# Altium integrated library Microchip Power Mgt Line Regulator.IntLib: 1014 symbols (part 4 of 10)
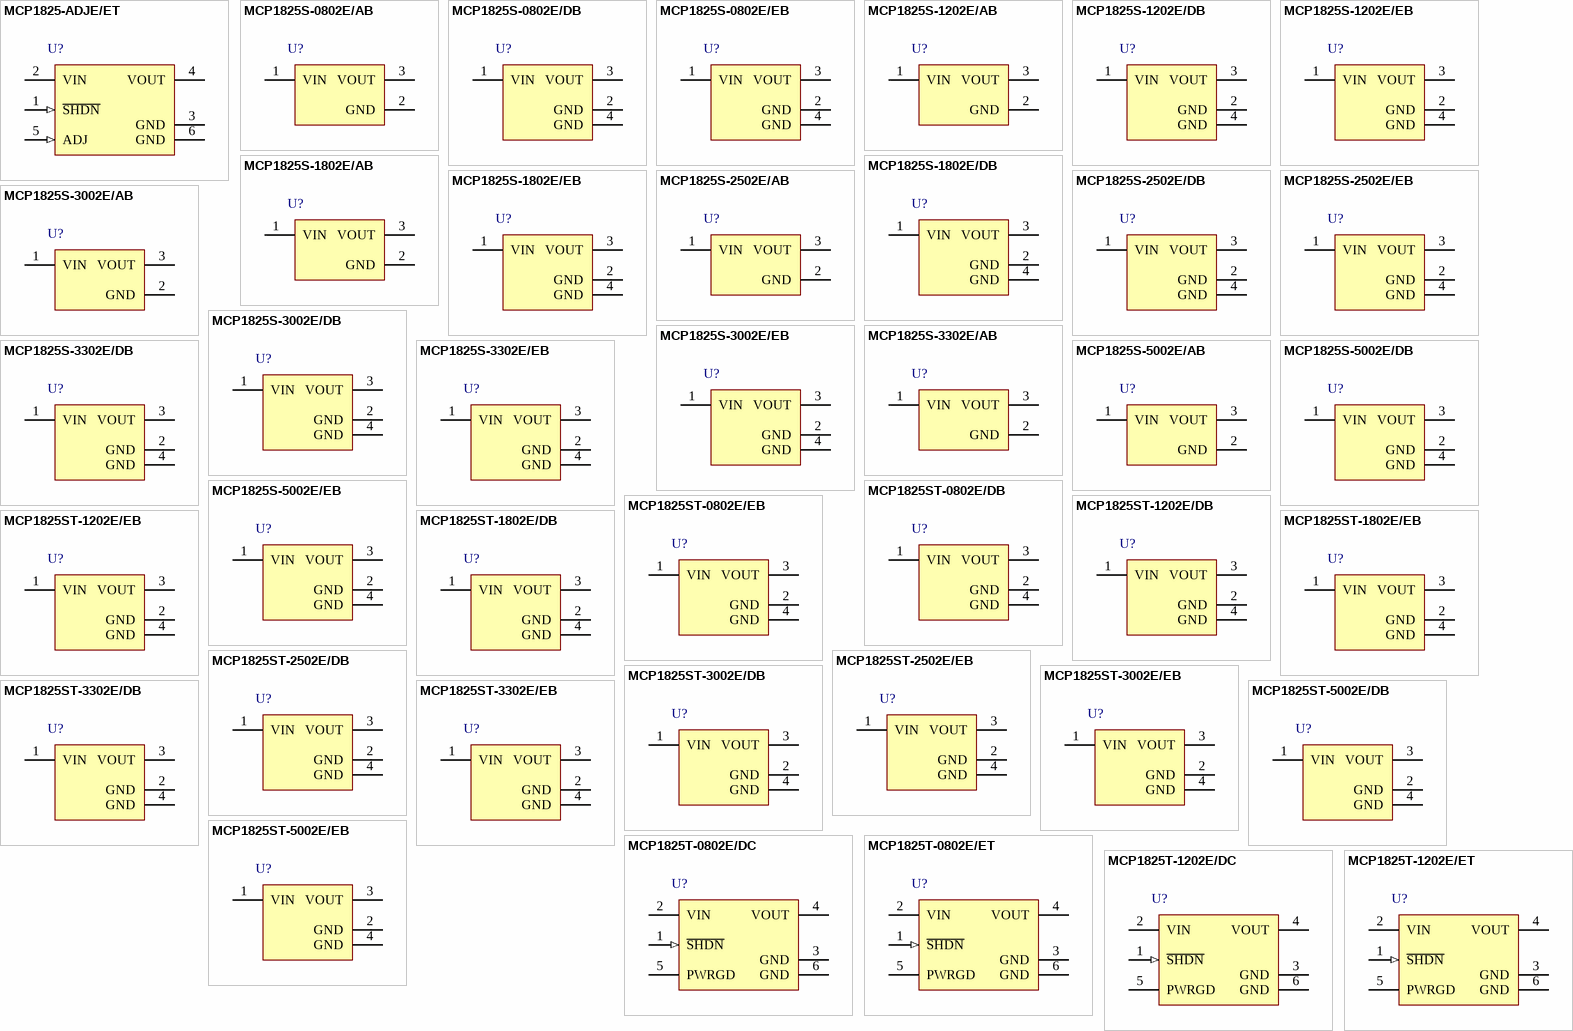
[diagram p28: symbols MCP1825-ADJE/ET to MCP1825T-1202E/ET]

## MCP1825S-1202E/EB
designator U?
500 mA, Low Voltage, Low Quiescent Current LDO Regulator, 3-Pin DDPAK, Extended Temperature
footprint DDPAK-EB3_N (D2-PAK, 4-Leads, Body 9x10.2mm, Pitch 2.54mm, Lead Span 14.9mm, IPC Medium Density)
footprint DDPAK-EB3_L (D2-PAK, 4-Leads, Body 9x10.2mm, Pitch 2.54mm, Lead Span 14.9mm, IPC High Density)
footprint DDPAK-EB3_M (D2-PAK, 4-Leads, Body 9x10.2mm, Pitch 2.54mm, Lead Span 14.9mm, IPC Low Density)
pins: 1 VIN (power), 2 GND (power), 3 VOUT (power), 4 GND (power)

## MCP1825S-1802E/AB
designator U?
500 mA, Low Voltage, Low Quiescent Current LDO Regulator, 3-Pin TO-220, Extended Temperature
footprint TO-220-AB3 (TO, Thru-Hole, Vertical, Heatsink Mounted; 3 In-Line Leads; Pitch 2.54 mm)
pins: 1 VIN (power), 2 GND (power), 3 VOUT (power)

## MCP1825S-1802E/DB
designator U?
500 mA, Low Voltage, Low Quiescent Current LDO Regulator, 3-Pin SOT-223, Extended Temperature
footprint SOT-223-DB3_N (SOT223, 4-Leads, Body 6.5x3.5mm, Pitch 2.3mm, Lead Span 7mm, IPC Medium Density)
footprint SOT-223-DB3_L (SOT223, 4-Leads, Body 6.5x3.5mm, Pitch 2.3mm, Lead Span 7mm, IPC High Density)
footprint SOT-223-DB3_M (SOT223, 4-Leads, Body 6.5x3.5mm, Pitch 2.3mm, Lead Span 7mm, IPC Low Density)
pins: 1 VIN (power), 2 GND (power), 3 VOUT (power), 4 GND (power)

## MCP1825S-1802E/EB
designator U?
500 mA, Low Voltage, Low Quiescent Current LDO Regulator, 3-Pin DDPAK, Extended Temperature
footprint DDPAK-EB3_N (D2-PAK, 4-Leads, Body 9x10.2mm, Pitch 2.54mm, Lead Span 14.9mm, IPC Medium Density)
footprint DDPAK-EB3_L (D2-PAK, 4-Leads, Body 9x10.2mm, Pitch 2.54mm, Lead Span 14.9mm, IPC High Density)
footprint DDPAK-EB3_M (D2-PAK, 4-Leads, Body 9x10.2mm, Pitch 2.54mm, Lead Span 14.9mm, IPC Low Density)
pins: 1 VIN (power), 2 GND (power), 3 VOUT (power), 4 GND (power)

## MCP1825S-2502E/AB
designator U?
500 mA, Low Voltage, Low Quiescent Current LDO Regulator, 3-Pin TO-220, Extended Temperature
footprint TO-220-AB3 (TO, Thru-Hole, Vertical, Heatsink Mounted; 3 In-Line Leads; Pitch 2.54 mm)
pins: 1 VIN (power), 2 GND (power), 3 VOUT (power)

## MCP1825S-2502E/DB
designator U?
500 mA, Low Voltage, Low Quiescent Current LDO Regulator, 3-Pin SOT-223, Extended Temperature
footprint SOT-223-DB3_N (SOT223, 4-Leads, Body 6.5x3.5mm, Pitch 2.3mm, Lead Span 7mm, IPC Medium Density)
footprint SOT-223-DB3_L (SOT223, 4-Leads, Body 6.5x3.5mm, Pitch 2.3mm, Lead Span 7mm, IPC High Density)
footprint SOT-223-DB3_M (SOT223, 4-Leads, Body 6.5x3.5mm, Pitch 2.3mm, Lead Span 7mm, IPC Low Density)
pins: 1 VIN (power), 2 GND (power), 3 VOUT (power), 4 GND (power)

## MCP1825S-2502E/EB
designator U?
500 mA, Low Voltage, Low Quiescent Current LDO Regulator, 3-Pin DDPAK, Extended Temperature
footprint DDPAK-EB3_N (D2-PAK, 4-Leads, Body 9x10.2mm, Pitch 2.54mm, Lead Span 14.9mm, IPC Medium Density)
footprint DDPAK-EB3_L (D2-PAK, 4-Leads, Body 9x10.2mm, Pitch 2.54mm, Lead Span 14.9mm, IPC High Density)
footprint DDPAK-EB3_M (D2-PAK, 4-Leads, Body 9x10.2mm, Pitch 2.54mm, Lead Span 14.9mm, IPC Low Density)
pins: 1 VIN (power), 2 GND (power), 3 VOUT (power), 4 GND (power)

## MCP1825S-3002E/AB
designator U?
500 mA, Low Voltage, Low Quiescent Current LDO Regulator, 3-Pin TO-220, Extended Temperature
footprint TO-220-AB3 (TO, Thru-Hole, Vertical, Heatsink Mounted; 3 In-Line Leads; Pitch 2.54 mm)
pins: 1 VIN (power), 2 GND (power), 3 VOUT (power)

## MCP1825S-3002E/DB
designator U?
500 mA, Low Voltage, Low Quiescent Current LDO Regulator, 3-Pin SOT-223, Extended Temperature
footprint SOT-223-DB3_N (SOT223, 4-Leads, Body 6.5x3.5mm, Pitch 2.3mm, Lead Span 7mm, IPC Medium Density)
footprint SOT-223-DB3_L (SOT223, 4-Leads, Body 6.5x3.5mm, Pitch 2.3mm, Lead Span 7mm, IPC High Density)
footprint SOT-223-DB3_M (SOT223, 4-Leads, Body 6.5x3.5mm, Pitch 2.3mm, Lead Span 7mm, IPC Low Density)
pins: 1 VIN (power), 2 GND (power), 3 VOUT (power), 4 GND (power)

## MCP1825S-3002E/EB
designator U?
500 mA, Low Voltage, Low Quiescent Current LDO Regulator, 3-Pin DDPAK, Extended Temperature
footprint DDPAK-EB3_N (D2-PAK, 4-Leads, Body 9x10.2mm, Pitch 2.54mm, Lead Span 14.9mm, IPC Medium Density)
footprint DDPAK-EB3_L (D2-PAK, 4-Leads, Body 9x10.2mm, Pitch 2.54mm, Lead Span 14.9mm, IPC High Density)
footprint DDPAK-EB3_M (D2-PAK, 4-Leads, Body 9x10.2mm, Pitch 2.54mm, Lead Span 14.9mm, IPC Low Density)
pins: 1 VIN (power), 2 GND (power), 3 VOUT (power), 4 GND (power)

## MCP1825S-3302E/AB
designator U?
500 mA, Low Voltage, Low Quiescent Current LDO Regulator, 3-Pin TO-220, Extended Temperature
footprint TO-220-AB3 (TO, Thru-Hole, Vertical, Heatsink Mounted; 3 In-Line Leads; Pitch 2.54 mm)
pins: 1 VIN (power), 2 GND (power), 3 VOUT (power)

## MCP1825S-3302E/DB
designator U?
500 mA, Low Voltage, Low Quiescent Current LDO Regulator, 3-Pin SOT-223, Extended Temperature
footprint SOT-223-DB3_N (SOT223, 4-Leads, Body 6.5x3.5mm, Pitch 2.3mm, Lead Span 7mm, IPC Medium Density)
footprint SOT-223-DB3_L (SOT223, 4-Leads, Body 6.5x3.5mm, Pitch 2.3mm, Lead Span 7mm, IPC High Density)
footprint SOT-223-DB3_M (SOT223, 4-Leads, Body 6.5x3.5mm, Pitch 2.3mm, Lead Span 7mm, IPC Low Density)
pins: 1 VIN (power), 2 GND (power), 3 VOUT (power), 4 GND (power)

## MCP1825S-3302E/EB
designator U?
500 mA, Low Voltage, Low Quiescent Current LDO Regulator, 3-Pin DDPAK, Extended Temperature
footprint DDPAK-EB3_N (D2-PAK, 4-Leads, Body 9x10.2mm, Pitch 2.54mm, Lead Span 14.9mm, IPC Medium Density)
footprint DDPAK-EB3_L (D2-PAK, 4-Leads, Body 9x10.2mm, Pitch 2.54mm, Lead Span 14.9mm, IPC High Density)
footprint DDPAK-EB3_M (D2-PAK, 4-Leads, Body 9x10.2mm, Pitch 2.54mm, Lead Span 14.9mm, IPC Low Density)
pins: 1 VIN (power), 2 GND (power), 3 VOUT (power), 4 GND (power)

## MCP1825S-5002E/AB
designator U?
500 mA, Low Voltage, Low Quiescent Current LDO Regulator, 3-Pin TO-220, Extended Temperature
footprint TO-220-AB3 (TO, Thru-Hole, Vertical, Heatsink Mounted; 3 In-Line Leads; Pitch 2.54 mm)
pins: 1 VIN (power), 2 GND (power), 3 VOUT (power)

## MCP1825S-5002E/DB
designator U?
500 mA, Low Voltage, Low Quiescent Current LDO Regulator, 3-Pin SOT-223, Extended Temperature
footprint SOT-223-DB3_N (SOT223, 4-Leads, Body 6.5x3.5mm, Pitch 2.3mm, Lead Span 7mm, IPC Medium Density)
footprint SOT-223-DB3_L (SOT223, 4-Leads, Body 6.5x3.5mm, Pitch 2.3mm, Lead Span 7mm, IPC High Density)
footprint SOT-223-DB3_M (SOT223, 4-Leads, Body 6.5x3.5mm, Pitch 2.3mm, Lead Span 7mm, IPC Low Density)
pins: 1 VIN (power), 2 GND (power), 3 VOUT (power), 4 GND (power)

## MCP1825S-5002E/EB
designator U?
500 mA, Low Voltage, Low Quiescent Current LDO Regulator, 3-Pin DDPAK, Extended Temperature
footprint DDPAK-EB3_N (D2-PAK, 4-Leads, Body 9x10.2mm, Pitch 2.54mm, Lead Span 14.9mm, IPC Medium Density)
footprint DDPAK-EB3_L (D2-PAK, 4-Leads, Body 9x10.2mm, Pitch 2.54mm, Lead Span 14.9mm, IPC High Density)
footprint DDPAK-EB3_M (D2-PAK, 4-Leads, Body 9x10.2mm, Pitch 2.54mm, Lead Span 14.9mm, IPC Low Density)
pins: 1 VIN (power), 2 GND (power), 3 VOUT (power), 4 GND (power)

## MCP1825ST-0802E/DB
designator U?
500 mA, Low Voltage, Low Quiescent Current LDO Regulator, 3-Pin SOT-223, Extended Temperature, Tape and Reel
footprint SOT-223-DB3_N (SOT223, 4-Leads, Body 6.5x3.5mm, Pitch 2.3mm, Lead Span 7mm, IPC Medium Density)
footprint SOT-223-DB3_L (SOT223, 4-Leads, Body 6.5x3.5mm, Pitch 2.3mm, Lead Span 7mm, IPC High Density)
footprint SOT-223-DB3_M (SOT223, 4-Leads, Body 6.5x3.5mm, Pitch 2.3mm, Lead Span 7mm, IPC Low Density)
pins: 1 VIN (power), 2 GND (power), 3 VOUT (power), 4 GND (power)

## MCP1825ST-0802E/EB
designator U?
500 mA, Low Voltage, Low Quiescent Current LDO Regulator, 3-Pin DDPAK, Extended Temperature, Tape and Reel
footprint DDPAK-EB3_N (D2-PAK, 4-Leads, Body 9x10.2mm, Pitch 2.54mm, Lead Span 14.9mm, IPC Medium Density)
footprint DDPAK-EB3_L (D2-PAK, 4-Leads, Body 9x10.2mm, Pitch 2.54mm, Lead Span 14.9mm, IPC High Density)
footprint DDPAK-EB3_M (D2-PAK, 4-Leads, Body 9x10.2mm, Pitch 2.54mm, Lead Span 14.9mm, IPC Low Density)
pins: 1 VIN (power), 2 GND (power), 3 VOUT (power), 4 GND (power)

## MCP1825ST-1202E/DB
designator U?
500 mA, Low Voltage, Low Quiescent Current LDO Regulator, 3-Pin SOT-223, Extended Temperature, Tape and Reel
footprint SOT-223-DB3_N (SOT223, 4-Leads, Body 6.5x3.5mm, Pitch 2.3mm, Lead Span 7mm, IPC Medium Density)
footprint SOT-223-DB3_L (SOT223, 4-Leads, Body 6.5x3.5mm, Pitch 2.3mm, Lead Span 7mm, IPC High Density)
footprint SOT-223-DB3_M (SOT223, 4-Leads, Body 6.5x3.5mm, Pitch 2.3mm, Lead Span 7mm, IPC Low Density)
pins: 1 VIN (power), 2 GND (power), 3 VOUT (power), 4 GND (power)

## MCP1825ST-1202E/EB
designator U?
500 mA, Low Voltage, Low Quiescent Current LDO Regulator, 3-Pin DDPAK, Extended Temperature, Tape and Reel
footprint DDPAK-EB3_N (D2-PAK, 4-Leads, Body 9x10.2mm, Pitch 2.54mm, Lead Span 14.9mm, IPC Medium Density)
footprint DDPAK-EB3_L (D2-PAK, 4-Leads, Body 9x10.2mm, Pitch 2.54mm, Lead Span 14.9mm, IPC High Density)
footprint DDPAK-EB3_M (D2-PAK, 4-Leads, Body 9x10.2mm, Pitch 2.54mm, Lead Span 14.9mm, IPC Low Density)
pins: 1 VIN (power), 2 GND (power), 3 VOUT (power), 4 GND (power)

## MCP1825ST-1802E/DB
designator U?
500 mA, Low Voltage, Low Quiescent Current LDO Regulator, 3-Pin SOT-223, Extended Temperature, Tape and Reel
footprint SOT-223-DB3_N (SOT223, 4-Leads, Body 6.5x3.5mm, Pitch 2.3mm, Lead Span 7mm, IPC Medium Density)
footprint SOT-223-DB3_L (SOT223, 4-Leads, Body 6.5x3.5mm, Pitch 2.3mm, Lead Span 7mm, IPC High Density)
footprint SOT-223-DB3_M (SOT223, 4-Leads, Body 6.5x3.5mm, Pitch 2.3mm, Lead Span 7mm, IPC Low Density)
pins: 1 VIN (power), 2 GND (power), 3 VOUT (power), 4 GND (power)

## MCP1825ST-1802E/EB
designator U?
500 mA, Low Voltage, Low Quiescent Current LDO Regulator, 3-Pin DDPAK, Extended Temperature, Tape and Reel
footprint DDPAK-EB3_N (D2-PAK, 4-Leads, Body 9x10.2mm, Pitch 2.54mm, Lead Span 14.9mm, IPC Medium Density)
footprint DDPAK-EB3_L (D2-PAK, 4-Leads, Body 9x10.2mm, Pitch 2.54mm, Lead Span 14.9mm, IPC High Density)
footprint DDPAK-EB3_M (D2-PAK, 4-Leads, Body 9x10.2mm, Pitch 2.54mm, Lead Span 14.9mm, IPC Low Density)
pins: 1 VIN (power), 2 GND (power), 3 VOUT (power), 4 GND (power)

## MCP1825ST-2502E/DB
designator U?
500 mA, Low Voltage, Low Quiescent Current LDO Regulator, 3-Pin SOT-223, Extended Temperature, Tape and Reel
footprint SOT-223-DB3_N (SOT223, 4-Leads, Body 6.5x3.5mm, Pitch 2.3mm, Lead Span 7mm, IPC Medium Density)
footprint SOT-223-DB3_L (SOT223, 4-Leads, Body 6.5x3.5mm, Pitch 2.3mm, Lead Span 7mm, IPC High Density)
footprint SOT-223-DB3_M (SOT223, 4-Leads, Body 6.5x3.5mm, Pitch 2.3mm, Lead Span 7mm, IPC Low Density)
pins: 1 VIN (power), 2 GND (power), 3 VOUT (power), 4 GND (power)

## MCP1825ST-2502E/EB
designator U?
500 mA, Low Voltage, Low Quiescent Current LDO Regulator, 3-Pin DDPAK, Extended Temperature, Tape and Reel
footprint DDPAK-EB3_N (D2-PAK, 4-Leads, Body 9x10.2mm, Pitch 2.54mm, Lead Span 14.9mm, IPC Medium Density)
footprint DDPAK-EB3_L (D2-PAK, 4-Leads, Body 9x10.2mm, Pitch 2.54mm, Lead Span 14.9mm, IPC High Density)
footprint DDPAK-EB3_M (D2-PAK, 4-Leads, Body 9x10.2mm, Pitch 2.54mm, Lead Span 14.9mm, IPC Low Density)
pins: 1 VIN (power), 2 GND (power), 3 VOUT (power), 4 GND (power)

## MCP1825ST-3002E/DB
designator U?
500 mA, Low Voltage, Low Quiescent Current LDO Regulator, 3-Pin SOT-223, Extended Temperature, Tape and Reel
footprint SOT-223-DB3_N (SOT223, 4-Leads, Body 6.5x3.5mm, Pitch 2.3mm, Lead Span 7mm, IPC Medium Density)
footprint SOT-223-DB3_L (SOT223, 4-Leads, Body 6.5x3.5mm, Pitch 2.3mm, Lead Span 7mm, IPC High Density)
footprint SOT-223-DB3_M (SOT223, 4-Leads, Body 6.5x3.5mm, Pitch 2.3mm, Lead Span 7mm, IPC Low Density)
pins: 1 VIN (power), 2 GND (power), 3 VOUT (power), 4 GND (power)

## MCP1825ST-3002E/EB
designator U?
500 mA, Low Voltage, Low Quiescent Current LDO Regulator, 3-Pin DDPAK, Extended Temperature, Tape and Reel
footprint DDPAK-EB3_N (D2-PAK, 4-Leads, Body 9x10.2mm, Pitch 2.54mm, Lead Span 14.9mm, IPC Medium Density)
footprint DDPAK-EB3_L (D2-PAK, 4-Leads, Body 9x10.2mm, Pitch 2.54mm, Lead Span 14.9mm, IPC High Density)
footprint DDPAK-EB3_M (D2-PAK, 4-Leads, Body 9x10.2mm, Pitch 2.54mm, Lead Span 14.9mm, IPC Low Density)
pins: 1 VIN (power), 2 GND (power), 3 VOUT (power), 4 GND (power)

## MCP1825ST-3302E/DB
designator U?
500 mA, Low Voltage, Low Quiescent Current LDO Regulator, 3-Pin SOT-223, Extended Temperature, Tape and Reel
footprint SOT-223-DB3_N (SOT223, 4-Leads, Body 6.5x3.5mm, Pitch 2.3mm, Lead Span 7mm, IPC Medium Density)
footprint SOT-223-DB3_L (SOT223, 4-Leads, Body 6.5x3.5mm, Pitch 2.3mm, Lead Span 7mm, IPC High Density)
footprint SOT-223-DB3_M (SOT223, 4-Leads, Body 6.5x3.5mm, Pitch 2.3mm, Lead Span 7mm, IPC Low Density)
pins: 1 VIN (power), 2 GND (power), 3 VOUT (power), 4 GND (power)

## MCP1825ST-3302E/EB
designator U?
500 mA, Low Voltage, Low Quiescent Current LDO Regulator, 3-Pin DDPAK, Extended Temperature, Tape and Reel
footprint DDPAK-EB3_N (D2-PAK, 4-Leads, Body 9x10.2mm, Pitch 2.54mm, Lead Span 14.9mm, IPC Medium Density)
footprint DDPAK-EB3_L (D2-PAK, 4-Leads, Body 9x10.2mm, Pitch 2.54mm, Lead Span 14.9mm, IPC High Density)
footprint DDPAK-EB3_M (D2-PAK, 4-Leads, Body 9x10.2mm, Pitch 2.54mm, Lead Span 14.9mm, IPC Low Density)
pins: 1 VIN (power), 2 GND (power), 3 VOUT (power), 4 GND (power)

## MCP1825ST-5002E/DB
designator U?
500 mA, Low Voltage, Low Quiescent Current LDO Regulator, 3-Pin SOT-223, Extended Temperature, Tape and Reel
footprint SOT-223-DB3_N (SOT223, 4-Leads, Body 6.5x3.5mm, Pitch 2.3mm, Lead Span 7mm, IPC Medium Density)
footprint SOT-223-DB3_L (SOT223, 4-Leads, Body 6.5x3.5mm, Pitch 2.3mm, Lead Span 7mm, IPC High Density)
footprint SOT-223-DB3_M (SOT223, 4-Leads, Body 6.5x3.5mm, Pitch 2.3mm, Lead Span 7mm, IPC Low Density)
pins: 1 VIN (power), 2 GND (power), 3 VOUT (power), 4 GND (power)

## MCP1825ST-5002E/EB
designator U?
500 mA, Low Voltage, Low Quiescent Current LDO Regulator, 3-Pin DDPAK, Extended Temperature, Tape and Reel
footprint DDPAK-EB3_N (D2-PAK, 4-Leads, Body 9x10.2mm, Pitch 2.54mm, Lead Span 14.9mm, IPC Medium Density)
footprint DDPAK-EB3_L (D2-PAK, 4-Leads, Body 9x10.2mm, Pitch 2.54mm, Lead Span 14.9mm, IPC High Density)
footprint DDPAK-EB3_M (D2-PAK, 4-Leads, Body 9x10.2mm, Pitch 2.54mm, Lead Span 14.9mm, IPC Low Density)
pins: 1 VIN (power), 2 GND (power), 3 VOUT (power), 4 GND (power)

## MCP1825T-0802E/DC
designator U?
500 mA, Low Voltage, Low Quiescent Current LDO Regulator, 5-Pin SOT-223, Extended Temperature, Tape and Reel
footprint SOT-223-DC5_N (SOT223, 6-Leads, Body 6.5x3.5mm, Pitch 1.27mm, Lead Span 7mm, IPC Medium Density)
footprint SOT-223-DC5_L (SOT223, 6-Leads, Body 6.5x3.5mm, Pitch 1.27mm, Lead Span 7mm, IPC High Density)
footprint SOT-223-DC5_M (SOT223, 6-Leads, Body 6.5x3.5mm, Pitch 1.27mm, Lead Span 7mm, IPC Low Density)
pins: 1 ~{SHDN} (in), 2 VIN (power), 3 GND (power), 4 VOUT (power), 5 PWRGD (power), 6 GND (power)

## MCP1825T-0802E/ET
designator U?
500 mA, Low Voltage, Low Quiescent Current LDO Regulator, 5-Pin DDPAK, Extended Temperature, Tape and Reel
footprint DDPAK-ET5_N (D2-PAK, 6-Leads, Body 9x10.2mm, Pitch 1.7mm, Lead Span 14.9mm, IPC Medium Density)
footprint DDPAK-ET5_L (D2-PAK, 6-Leads, Body 9x10.2mm, Pitch 1.7mm, Lead Span 14.9mm, IPC High Density)
footprint DDPAK-ET5_M (D2-PAK, 6-Leads, Body 9x10.2mm, Pitch 1.7mm, Lead Span 14.9mm, IPC Low Density)
pins: 1 ~{SHDN} (in), 2 VIN (power), 3 GND (power), 4 VOUT (power), 5 PWRGD (power), 6 GND (power)

## MCP1825T-1202E/DC
designator U?
500 mA, Low Voltage, Low Quiescent Current LDO Regulator, 5-Pin SOT-223, Extended Temperature, Tape and Reel
footprint SOT-223-DC5_N (SOT223, 6-Leads, Body 6.5x3.5mm, Pitch 1.27mm, Lead Span 7mm, IPC Medium Density)
footprint SOT-223-DC5_L (SOT223, 6-Leads, Body 6.5x3.5mm, Pitch 1.27mm, Lead Span 7mm, IPC High Density)
footprint SOT-223-DC5_M (SOT223, 6-Leads, Body 6.5x3.5mm, Pitch 1.27mm, Lead Span 7mm, IPC Low Density)
pins: 1 ~{SHDN} (in), 2 VIN (power), 3 GND (power), 4 VOUT (power), 5 PWRGD (power), 6 GND (power)

## MCP1825T-1202E/ET
designator U?
500 mA, Low Voltage, Low Quiescent Current LDO Regulator, 5-Pin DDPAK, Extended Temperature, Tape and Reel
footprint DDPAK-ET5_N (D2-PAK, 6-Leads, Body 9x10.2mm, Pitch 1.7mm, Lead Span 14.9mm, IPC Medium Density)
footprint DDPAK-ET5_L (D2-PAK, 6-Leads, Body 9x10.2mm, Pitch 1.7mm, Lead Span 14.9mm, IPC High Density)
footprint DDPAK-ET5_M (D2-PAK, 6-Leads, Body 9x10.2mm, Pitch 1.7mm, Lead Span 14.9mm, IPC Low Density)
pins: 1 ~{SHDN} (in), 2 VIN (power), 3 GND (power), 4 VOUT (power), 5 PWRGD (power), 6 GND (power)

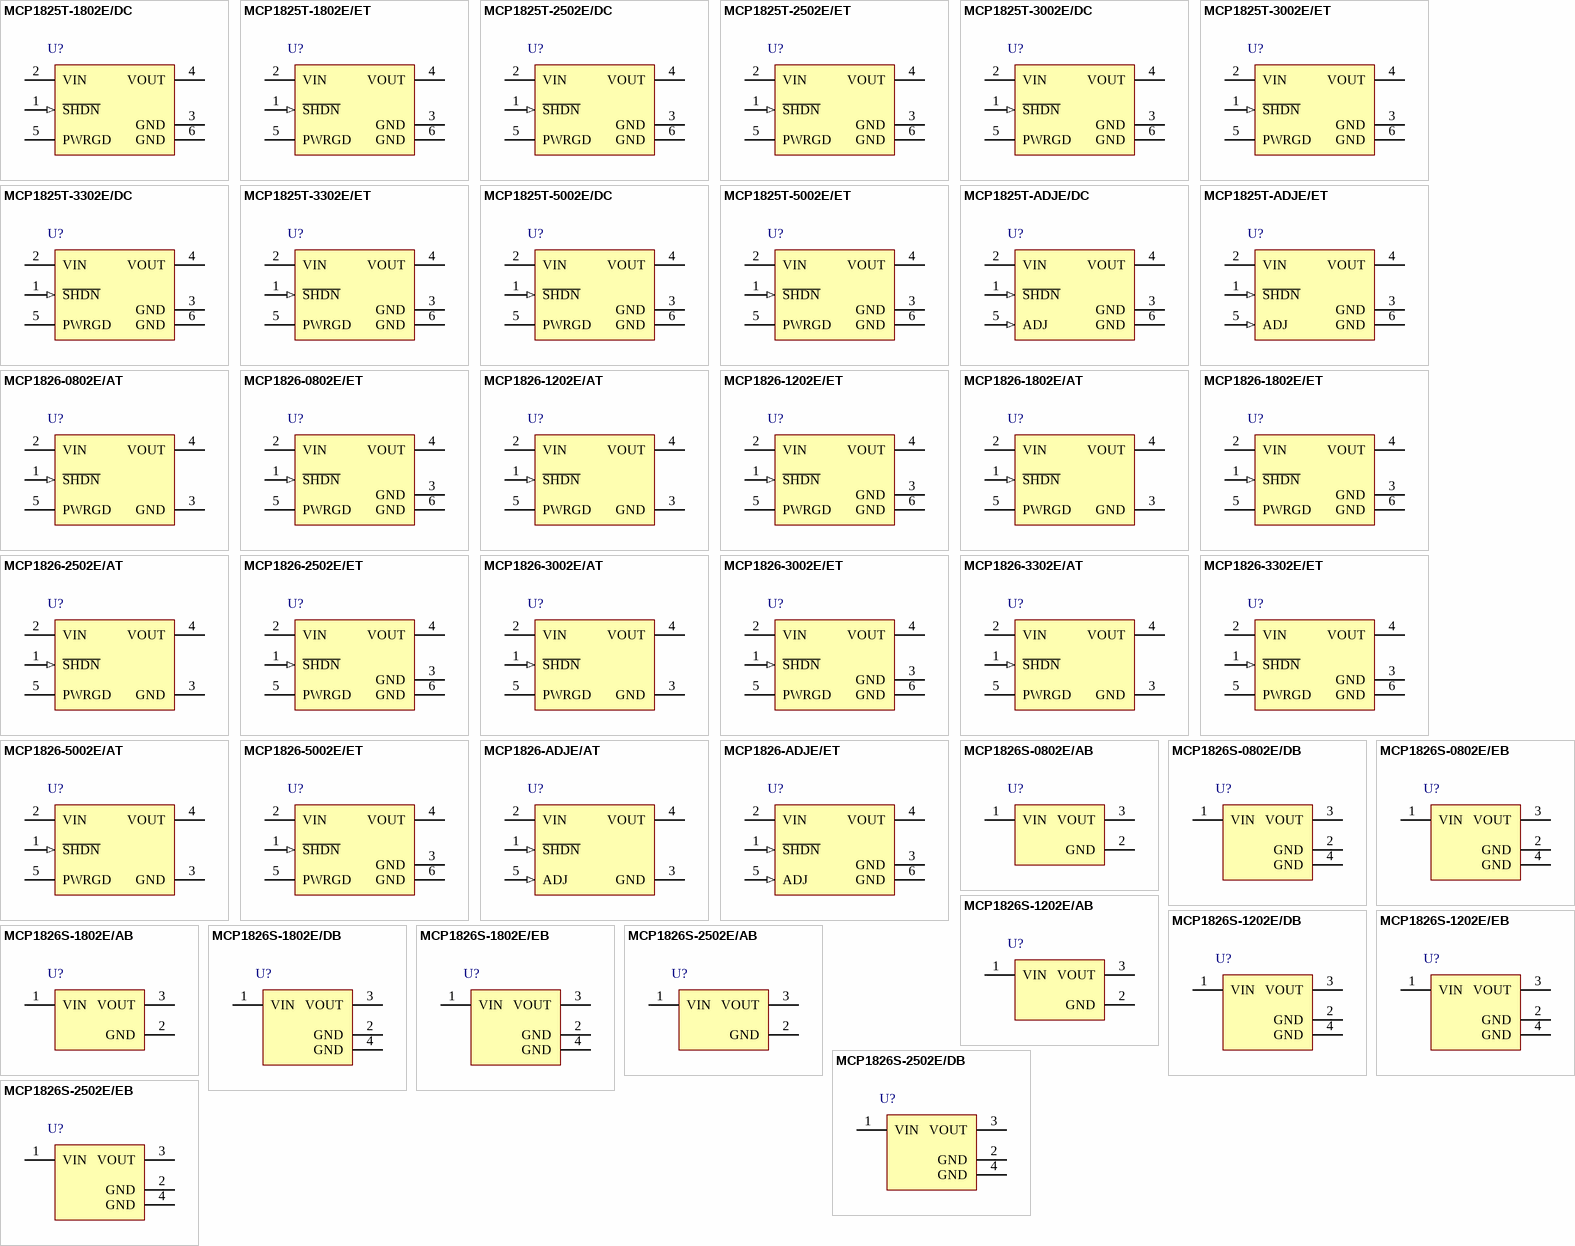
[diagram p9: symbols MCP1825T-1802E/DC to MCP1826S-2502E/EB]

## MCP1825T-1802E/DC
designator U?
500 mA, Low Voltage, Low Quiescent Current LDO Regulator, 5-Pin SOT-223, Extended Temperature, Tape and Reel
footprint SOT-223-DC5_N (SOT223, 6-Leads, Body 6.5x3.5mm, Pitch 1.27mm, Lead Span 7mm, IPC Medium Density)
footprint SOT-223-DC5_L (SOT223, 6-Leads, Body 6.5x3.5mm, Pitch 1.27mm, Lead Span 7mm, IPC High Density)
footprint SOT-223-DC5_M (SOT223, 6-Leads, Body 6.5x3.5mm, Pitch 1.27mm, Lead Span 7mm, IPC Low Density)
pins: 1 ~{SHDN} (in), 2 VIN (power), 3 GND (power), 4 VOUT (power), 5 PWRGD (power), 6 GND (power)

## MCP1825T-1802E/ET
designator U?
500 mA, Low Voltage, Low Quiescent Current LDO Regulator, 5-Pin DDPAK, Extended Temperature, Tape and Reel
footprint DDPAK-ET5_N (D2-PAK, 6-Leads, Body 9x10.2mm, Pitch 1.7mm, Lead Span 14.9mm, IPC Medium Density)
footprint DDPAK-ET5_L (D2-PAK, 6-Leads, Body 9x10.2mm, Pitch 1.7mm, Lead Span 14.9mm, IPC High Density)
footprint DDPAK-ET5_M (D2-PAK, 6-Leads, Body 9x10.2mm, Pitch 1.7mm, Lead Span 14.9mm, IPC Low Density)
pins: 1 ~{SHDN} (in), 2 VIN (power), 3 GND (power), 4 VOUT (power), 5 PWRGD (power), 6 GND (power)

## MCP1825T-2502E/DC
designator U?
500 mA, Low Voltage, Low Quiescent Current LDO Regulator, 5-Pin SOT-223, Extended Temperature, Tape and Reel
footprint SOT-223-DC5_N (SOT223, 6-Leads, Body 6.5x3.5mm, Pitch 1.27mm, Lead Span 7mm, IPC Medium Density)
footprint SOT-223-DC5_L (SOT223, 6-Leads, Body 6.5x3.5mm, Pitch 1.27mm, Lead Span 7mm, IPC High Density)
footprint SOT-223-DC5_M (SOT223, 6-Leads, Body 6.5x3.5mm, Pitch 1.27mm, Lead Span 7mm, IPC Low Density)
pins: 1 ~{SHDN} (in), 2 VIN (power), 3 GND (power), 4 VOUT (power), 5 PWRGD (power), 6 GND (power)

## MCP1825T-2502E/ET
designator U?
500 mA, Low Voltage, Low Quiescent Current LDO Regulator, 5-Pin DDPAK, Extended Temperature, Tape and Reel
footprint DDPAK-ET5_N (D2-PAK, 6-Leads, Body 9x10.2mm, Pitch 1.7mm, Lead Span 14.9mm, IPC Medium Density)
footprint DDPAK-ET5_L (D2-PAK, 6-Leads, Body 9x10.2mm, Pitch 1.7mm, Lead Span 14.9mm, IPC High Density)
footprint DDPAK-ET5_M (D2-PAK, 6-Leads, Body 9x10.2mm, Pitch 1.7mm, Lead Span 14.9mm, IPC Low Density)
pins: 1 ~{SHDN} (in), 2 VIN (power), 3 GND (power), 4 VOUT (power), 5 PWRGD (power), 6 GND (power)

## MCP1825T-3002E/DC
designator U?
500 mA, Low Voltage, Low Quiescent Current LDO Regulator, 5-Pin SOT-223, Extended Temperature, Tape and Reel
footprint SOT-223-DC5_N (SOT223, 6-Leads, Body 6.5x3.5mm, Pitch 1.27mm, Lead Span 7mm, IPC Medium Density)
footprint SOT-223-DC5_L (SOT223, 6-Leads, Body 6.5x3.5mm, Pitch 1.27mm, Lead Span 7mm, IPC High Density)
footprint SOT-223-DC5_M (SOT223, 6-Leads, Body 6.5x3.5mm, Pitch 1.27mm, Lead Span 7mm, IPC Low Density)
pins: 1 ~{SHDN} (in), 2 VIN (power), 3 GND (power), 4 VOUT (power), 5 PWRGD (power), 6 GND (power)

## MCP1825T-3002E/ET
designator U?
500 mA, Low Voltage, Low Quiescent Current LDO Regulator, 5-Pin DDPAK, Extended Temperature, Tape and Reel
footprint DDPAK-ET5_N (D2-PAK, 6-Leads, Body 9x10.2mm, Pitch 1.7mm, Lead Span 14.9mm, IPC Medium Density)
footprint DDPAK-ET5_L (D2-PAK, 6-Leads, Body 9x10.2mm, Pitch 1.7mm, Lead Span 14.9mm, IPC High Density)
footprint DDPAK-ET5_M (D2-PAK, 6-Leads, Body 9x10.2mm, Pitch 1.7mm, Lead Span 14.9mm, IPC Low Density)
pins: 1 ~{SHDN} (in), 2 VIN (power), 3 GND (power), 4 VOUT (power), 5 PWRGD (power), 6 GND (power)

## MCP1825T-3302E/DC
designator U?
500 mA, Low Voltage, Low Quiescent Current LDO Regulator, 5-Pin SOT-223, Extended Temperature, Tape and Reel
footprint SOT-223-DC5_N (SOT223, 6-Leads, Body 6.5x3.5mm, Pitch 1.27mm, Lead Span 7mm, IPC Medium Density)
footprint SOT-223-DC5_L (SOT223, 6-Leads, Body 6.5x3.5mm, Pitch 1.27mm, Lead Span 7mm, IPC High Density)
footprint SOT-223-DC5_M (SOT223, 6-Leads, Body 6.5x3.5mm, Pitch 1.27mm, Lead Span 7mm, IPC Low Density)
pins: 1 ~{SHDN} (in), 2 VIN (power), 3 GND (power), 4 VOUT (power), 5 PWRGD (power), 6 GND (power)

## MCP1825T-3302E/ET
designator U?
500 mA, Low Voltage, Low Quiescent Current LDO Regulator, 5-Pin DDPAK, Extended Temperature, Tape and Reel
footprint DDPAK-ET5_N (D2-PAK, 6-Leads, Body 9x10.2mm, Pitch 1.7mm, Lead Span 14.9mm, IPC Medium Density)
footprint DDPAK-ET5_L (D2-PAK, 6-Leads, Body 9x10.2mm, Pitch 1.7mm, Lead Span 14.9mm, IPC High Density)
footprint DDPAK-ET5_M (D2-PAK, 6-Leads, Body 9x10.2mm, Pitch 1.7mm, Lead Span 14.9mm, IPC Low Density)
pins: 1 ~{SHDN} (in), 2 VIN (power), 3 GND (power), 4 VOUT (power), 5 PWRGD (power), 6 GND (power)

## MCP1825T-5002E/DC
designator U?
500 mA, Low Voltage, Low Quiescent Current LDO Regulator, 5-Pin SOT-223, Extended Temperature, Tape and Reel
footprint SOT-223-DC5_N (SOT223, 6-Leads, Body 6.5x3.5mm, Pitch 1.27mm, Lead Span 7mm, IPC Medium Density)
footprint SOT-223-DC5_L (SOT223, 6-Leads, Body 6.5x3.5mm, Pitch 1.27mm, Lead Span 7mm, IPC High Density)
footprint SOT-223-DC5_M (SOT223, 6-Leads, Body 6.5x3.5mm, Pitch 1.27mm, Lead Span 7mm, IPC Low Density)
pins: 1 ~{SHDN} (in), 2 VIN (power), 3 GND (power), 4 VOUT (power), 5 PWRGD (power), 6 GND (power)

## MCP1825T-5002E/ET
designator U?
500 mA, Low Voltage, Low Quiescent Current LDO Regulator, 5-Pin DDPAK, Extended Temperature, Tape and Reel
footprint DDPAK-ET5_N (D2-PAK, 6-Leads, Body 9x10.2mm, Pitch 1.7mm, Lead Span 14.9mm, IPC Medium Density)
footprint DDPAK-ET5_L (D2-PAK, 6-Leads, Body 9x10.2mm, Pitch 1.7mm, Lead Span 14.9mm, IPC High Density)
footprint DDPAK-ET5_M (D2-PAK, 6-Leads, Body 9x10.2mm, Pitch 1.7mm, Lead Span 14.9mm, IPC Low Density)
pins: 1 ~{SHDN} (in), 2 VIN (power), 3 GND (power), 4 VOUT (power), 5 PWRGD (power), 6 GND (power)

## MCP1825T-ADJE/DC
designator U?
500 mA, Low Voltage, Low Quiescent Current LDO Regulator, 5-Pin SOT-223, Extended Temperature, Tape and Reel
footprint SOT-223-DC5_N (SOT223, 6-Leads, Body 6.5x3.5mm, Pitch 1.27mm, Lead Span 7mm, IPC Medium Density)
footprint SOT-223-DC5_L (SOT223, 6-Leads, Body 6.5x3.5mm, Pitch 1.27mm, Lead Span 7mm, IPC High Density)
footprint SOT-223-DC5_M (SOT223, 6-Leads, Body 6.5x3.5mm, Pitch 1.27mm, Lead Span 7mm, IPC Low Density)
pins: 1 ~{SHDN} (in), 2 VIN (power), 3 GND (power), 4 VOUT (power), 5 ADJ (in), 6 GND (power)

## MCP1825T-ADJE/ET
designator U?
500 mA, Low Voltage, Low Quiescent Current LDO Regulator, 5-Pin DDPAK, Extended Temperature, Tape and Reel
footprint DDPAK-ET5_N (D2-PAK, 6-Leads, Body 9x10.2mm, Pitch 1.7mm, Lead Span 14.9mm, IPC Medium Density)
footprint DDPAK-ET5_L (D2-PAK, 6-Leads, Body 9x10.2mm, Pitch 1.7mm, Lead Span 14.9mm, IPC High Density)
footprint DDPAK-ET5_M (D2-PAK, 6-Leads, Body 9x10.2mm, Pitch 1.7mm, Lead Span 14.9mm, IPC Low Density)
pins: 1 ~{SHDN} (in), 2 VIN (power), 3 GND (power), 4 VOUT (power), 5 ADJ (in), 6 GND (power)

## MCP1826-0802E/AT
designator U?
1000 mA, Low Voltage, Low Quiescent Current LDO Regulator, 5-Pin TO-220, Extended Temperature
footprint TO-220-AT5 (TO, Thru-Hole, Vertical, Heatsink Mounted; 5 In-Line Leads; Pitch 1.70 mm)
pins: 1 ~{SHDN} (in), 2 VIN (power), 3 GND (power), 4 VOUT (power), 5 PWRGD (power)

## MCP1826-0802E/ET
designator U?
1000 mA, Low Voltage, Low Quiescent Current LDO Regulator, 5-Pin DDPAK, Extended Temperature
footprint DDPAK-ET5_N (D2-PAK, 6-Leads, Body 9x10.2mm, Pitch 1.7mm, Lead Span 14.9mm, IPC Medium Density)
footprint DDPAK-ET5_L (D2-PAK, 6-Leads, Body 9x10.2mm, Pitch 1.7mm, Lead Span 14.9mm, IPC High Density)
footprint DDPAK-ET5_M (D2-PAK, 6-Leads, Body 9x10.2mm, Pitch 1.7mm, Lead Span 14.9mm, IPC Low Density)
pins: 1 ~{SHDN} (in), 2 VIN (power), 3 GND (power), 4 VOUT (power), 5 PWRGD (power), 6 GND (power)

## MCP1826-1202E/AT
designator U?
1000 mA, Low Voltage, Low Quiescent Current LDO Regulator, 5-Pin TO-220, Extended Temperature
footprint TO-220-AT5 (TO, Thru-Hole, Vertical, Heatsink Mounted; 5 In-Line Leads; Pitch 1.70 mm)
pins: 1 ~{SHDN} (in), 2 VIN (power), 3 GND (power), 4 VOUT (power), 5 PWRGD (power)

## MCP1826-1202E/ET
designator U?
1000 mA, Low Voltage, Low Quiescent Current LDO Regulator, 5-Pin DDPAK, Extended Temperature
footprint DDPAK-ET5_N (D2-PAK, 6-Leads, Body 9x10.2mm, Pitch 1.7mm, Lead Span 14.9mm, IPC Medium Density)
footprint DDPAK-ET5_L (D2-PAK, 6-Leads, Body 9x10.2mm, Pitch 1.7mm, Lead Span 14.9mm, IPC High Density)
footprint DDPAK-ET5_M (D2-PAK, 6-Leads, Body 9x10.2mm, Pitch 1.7mm, Lead Span 14.9mm, IPC Low Density)
pins: 1 ~{SHDN} (in), 2 VIN (power), 3 GND (power), 4 VOUT (power), 5 PWRGD (power), 6 GND (power)

## MCP1826-1802E/AT
designator U?
1000 mA, Low Voltage, Low Quiescent Current LDO Regulator, 5-Pin TO-220, Extended Temperature
footprint TO-220-AT5 (TO, Thru-Hole, Vertical, Heatsink Mounted; 5 In-Line Leads; Pitch 1.70 mm)
pins: 1 ~{SHDN} (in), 2 VIN (power), 3 GND (power), 4 VOUT (power), 5 PWRGD (power)

## MCP1826-1802E/ET
designator U?
1000 mA, Low Voltage, Low Quiescent Current LDO Regulator, 5-Pin DDPAK, Extended Temperature
footprint DDPAK-ET5_N (D2-PAK, 6-Leads, Body 9x10.2mm, Pitch 1.7mm, Lead Span 14.9mm, IPC Medium Density)
footprint DDPAK-ET5_L (D2-PAK, 6-Leads, Body 9x10.2mm, Pitch 1.7mm, Lead Span 14.9mm, IPC High Density)
footprint DDPAK-ET5_M (D2-PAK, 6-Leads, Body 9x10.2mm, Pitch 1.7mm, Lead Span 14.9mm, IPC Low Density)
pins: 1 ~{SHDN} (in), 2 VIN (power), 3 GND (power), 4 VOUT (power), 5 PWRGD (power), 6 GND (power)

## MCP1826-2502E/AT
designator U?
1000 mA, Low Voltage, Low Quiescent Current LDO Regulator, 5-Pin TO-220, Extended Temperature
footprint TO-220-AT5 (TO, Thru-Hole, Vertical, Heatsink Mounted; 5 In-Line Leads; Pitch 1.70 mm)
pins: 1 ~{SHDN} (in), 2 VIN (power), 3 GND (power), 4 VOUT (power), 5 PWRGD (power)

## MCP1826-2502E/ET
designator U?
1000 mA, Low Voltage, Low Quiescent Current LDO Regulator, 5-Pin DDPAK, Extended Temperature
footprint DDPAK-ET5_N (D2-PAK, 6-Leads, Body 9x10.2mm, Pitch 1.7mm, Lead Span 14.9mm, IPC Medium Density)
footprint DDPAK-ET5_L (D2-PAK, 6-Leads, Body 9x10.2mm, Pitch 1.7mm, Lead Span 14.9mm, IPC High Density)
footprint DDPAK-ET5_M (D2-PAK, 6-Leads, Body 9x10.2mm, Pitch 1.7mm, Lead Span 14.9mm, IPC Low Density)
pins: 1 ~{SHDN} (in), 2 VIN (power), 3 GND (power), 4 VOUT (power), 5 PWRGD (power), 6 GND (power)

## MCP1826-3002E/AT
designator U?
1000 mA, Low Voltage, Low Quiescent Current LDO Regulator, 5-Pin TO-220, Extended Temperature
footprint TO-220-AT5 (TO, Thru-Hole, Vertical, Heatsink Mounted; 5 In-Line Leads; Pitch 1.70 mm)
pins: 1 ~{SHDN} (in), 2 VIN (power), 3 GND (power), 4 VOUT (power), 5 PWRGD (power)

## MCP1826-3002E/ET
designator U?
1000 mA, Low Voltage, Low Quiescent Current LDO Regulator, 5-Pin DDPAK, Extended Temperature
footprint DDPAK-ET5_N (D2-PAK, 6-Leads, Body 9x10.2mm, Pitch 1.7mm, Lead Span 14.9mm, IPC Medium Density)
footprint DDPAK-ET5_L (D2-PAK, 6-Leads, Body 9x10.2mm, Pitch 1.7mm, Lead Span 14.9mm, IPC High Density)
footprint DDPAK-ET5_M (D2-PAK, 6-Leads, Body 9x10.2mm, Pitch 1.7mm, Lead Span 14.9mm, IPC Low Density)
pins: 1 ~{SHDN} (in), 2 VIN (power), 3 GND (power), 4 VOUT (power), 5 PWRGD (power), 6 GND (power)

## MCP1826-3302E/AT
designator U?
1000 mA, Low Voltage, Low Quiescent Current LDO Regulator, 5-Pin TO-220, Extended Temperature
footprint TO-220-AT5 (TO, Thru-Hole, Vertical, Heatsink Mounted; 5 In-Line Leads; Pitch 1.70 mm)
pins: 1 ~{SHDN} (in), 2 VIN (power), 3 GND (power), 4 VOUT (power), 5 PWRGD (power)

## MCP1826-3302E/ET
designator U?
1000 mA, Low Voltage, Low Quiescent Current LDO Regulator, 5-Pin DDPAK, Extended Temperature
footprint DDPAK-ET5_N (D2-PAK, 6-Leads, Body 9x10.2mm, Pitch 1.7mm, Lead Span 14.9mm, IPC Medium Density)
footprint DDPAK-ET5_L (D2-PAK, 6-Leads, Body 9x10.2mm, Pitch 1.7mm, Lead Span 14.9mm, IPC High Density)
footprint DDPAK-ET5_M (D2-PAK, 6-Leads, Body 9x10.2mm, Pitch 1.7mm, Lead Span 14.9mm, IPC Low Density)
pins: 1 ~{SHDN} (in), 2 VIN (power), 3 GND (power), 4 VOUT (power), 5 PWRGD (power), 6 GND (power)

## MCP1826-5002E/AT
designator U?
1000 mA, Low Voltage, Low Quiescent Current LDO Regulator, 5-Pin TO-220, Extended Temperature
footprint TO-220-AT5 (TO, Thru-Hole, Vertical, Heatsink Mounted; 5 In-Line Leads; Pitch 1.70 mm)
pins: 1 ~{SHDN} (in), 2 VIN (power), 3 GND (power), 4 VOUT (power), 5 PWRGD (power)

## MCP1826-5002E/ET
designator U?
1000 mA, Low Voltage, Low Quiescent Current LDO Regulator, 5-Pin DDPAK, Extended Temperature
footprint DDPAK-ET5_N (D2-PAK, 6-Leads, Body 9x10.2mm, Pitch 1.7mm, Lead Span 14.9mm, IPC Medium Density)
footprint DDPAK-ET5_L (D2-PAK, 6-Leads, Body 9x10.2mm, Pitch 1.7mm, Lead Span 14.9mm, IPC High Density)
footprint DDPAK-ET5_M (D2-PAK, 6-Leads, Body 9x10.2mm, Pitch 1.7mm, Lead Span 14.9mm, IPC Low Density)
pins: 1 ~{SHDN} (in), 2 VIN (power), 3 GND (power), 4 VOUT (power), 5 PWRGD (power), 6 GND (power)

## MCP1826-ADJE/AT
designator U?
1000 mA, Low Voltage, Low Quiescent Current LDO Regulator, 5-Pin TO-220, Extended Temperature
footprint TO-220-AT5 (TO, Thru-Hole, Vertical, Heatsink Mounted; 5 In-Line Leads; Pitch 1.70 mm)
pins: 1 ~{SHDN} (in), 2 VIN (power), 3 GND (power), 4 VOUT (power), 5 ADJ (in)

## MCP1826-ADJE/ET
designator U?
1000 mA, Low Voltage, Low Quiescent Current LDO Regulator, 5-Pin DDPAK, Extended Temperature
footprint DDPAK-ET5_N (D2-PAK, 6-Leads, Body 9x10.2mm, Pitch 1.7mm, Lead Span 14.9mm, IPC Medium Density)
footprint DDPAK-ET5_L (D2-PAK, 6-Leads, Body 9x10.2mm, Pitch 1.7mm, Lead Span 14.9mm, IPC High Density)
footprint DDPAK-ET5_M (D2-PAK, 6-Leads, Body 9x10.2mm, Pitch 1.7mm, Lead Span 14.9mm, IPC Low Density)
pins: 1 ~{SHDN} (in), 2 VIN (power), 3 GND (power), 4 VOUT (power), 5 ADJ (in), 6 GND (power)

## MCP1826S-0802E/AB
designator U?
1000 mA, Low Voltage, Low Quiescent Current LDO Regulator, 3-Pin TO-220, Extended Temperature
footprint TO-220-AB3 (TO, Thru-Hole, Vertical, Heatsink Mounted; 3 In-Line Leads; Pitch 2.54 mm)
pins: 1 VIN (power), 2 GND (power), 3 VOUT (power)

## MCP1826S-0802E/DB
designator U?
1000 mA, Low Voltage, Low Quiescent Current LDO Regulator, 3-Pin SOT-223, Extended Temperature
footprint SOT-223-DB3_N (SOT223, 4-Leads, Body 6.5x3.5mm, Pitch 2.3mm, Lead Span 7mm, IPC Medium Density)
footprint SOT-223-DB3_L (SOT223, 4-Leads, Body 6.5x3.5mm, Pitch 2.3mm, Lead Span 7mm, IPC High Density)
footprint SOT-223-DB3_M (SOT223, 4-Leads, Body 6.5x3.5mm, Pitch 2.3mm, Lead Span 7mm, IPC Low Density)
pins: 1 VIN (power), 2 GND (power), 3 VOUT (power), 4 GND (power)

## MCP1826S-0802E/EB
designator U?
1000 mA, Low Voltage, Low Quiescent Current LDO Regulator, 3-Pin DDPAK, Extended Temperature
footprint DDPAK-EB3_N (D2-PAK, 4-Leads, Body 9x10.2mm, Pitch 2.54mm, Lead Span 14.9mm, IPC Medium Density)
footprint DDPAK-EB3_L (D2-PAK, 4-Leads, Body 9x10.2mm, Pitch 2.54mm, Lead Span 14.9mm, IPC High Density)
footprint DDPAK-EB3_M (D2-PAK, 4-Leads, Body 9x10.2mm, Pitch 2.54mm, Lead Span 14.9mm, IPC Low Density)
pins: 1 VIN (power), 2 GND (power), 3 VOUT (power), 4 GND (power)

## MCP1826S-1202E/AB
designator U?
1000 mA, Low Voltage, Low Quiescent Current LDO Regulator, 3-Pin TO-220, Extended Temperature
footprint TO-220-AB3 (TO, Thru-Hole, Vertical, Heatsink Mounted; 3 In-Line Leads; Pitch 2.54 mm)
pins: 1 VIN (power), 2 GND (power), 3 VOUT (power)

## MCP1826S-1202E/DB
designator U?
1000 mA, Low Voltage, Low Quiescent Current LDO Regulator, 3-Pin SOT-223, Extended Temperature
footprint SOT-223-DB3_N (SOT223, 4-Leads, Body 6.5x3.5mm, Pitch 2.3mm, Lead Span 7mm, IPC Medium Density)
footprint SOT-223-DB3_L (SOT223, 4-Leads, Body 6.5x3.5mm, Pitch 2.3mm, Lead Span 7mm, IPC High Density)
footprint SOT-223-DB3_M (SOT223, 4-Leads, Body 6.5x3.5mm, Pitch 2.3mm, Lead Span 7mm, IPC Low Density)
pins: 1 VIN (power), 2 GND (power), 3 VOUT (power), 4 GND (power)

## MCP1826S-1202E/EB
designator U?
1000 mA, Low Voltage, Low Quiescent Current LDO Regulator, 3-Pin DDPAK, Extended Temperature
footprint DDPAK-EB3_N (D2-PAK, 4-Leads, Body 9x10.2mm, Pitch 2.54mm, Lead Span 14.9mm, IPC Medium Density)
footprint DDPAK-EB3_L (D2-PAK, 4-Leads, Body 9x10.2mm, Pitch 2.54mm, Lead Span 14.9mm, IPC High Density)
footprint DDPAK-EB3_M (D2-PAK, 4-Leads, Body 9x10.2mm, Pitch 2.54mm, Lead Span 14.9mm, IPC Low Density)
pins: 1 VIN (power), 2 GND (power), 3 VOUT (power), 4 GND (power)

## MCP1826S-1802E/AB
designator U?
1000 mA, Low Voltage, Low Quiescent Current LDO Regulator, 3-Pin TO-220, Extended Temperature
footprint TO-220-AB3 (TO, Thru-Hole, Vertical, Heatsink Mounted; 3 In-Line Leads; Pitch 2.54 mm)
pins: 1 VIN (power), 2 GND (power), 3 VOUT (power)

## MCP1826S-1802E/DB
designator U?
1000 mA, Low Voltage, Low Quiescent Current LDO Regulator, 3-Pin SOT-223, Extended Temperature
footprint SOT-223-DB3_N (SOT223, 4-Leads, Body 6.5x3.5mm, Pitch 2.3mm, Lead Span 7mm, IPC Medium Density)
footprint SOT-223-DB3_L (SOT223, 4-Leads, Body 6.5x3.5mm, Pitch 2.3mm, Lead Span 7mm, IPC High Density)
footprint SOT-223-DB3_M (SOT223, 4-Leads, Body 6.5x3.5mm, Pitch 2.3mm, Lead Span 7mm, IPC Low Density)
pins: 1 VIN (power), 2 GND (power), 3 VOUT (power), 4 GND (power)

## MCP1826S-1802E/EB
designator U?
1000 mA, Low Voltage, Low Quiescent Current LDO Regulator, 3-Pin DDPAK, Extended Temperature
footprint DDPAK-EB3_N (D2-PAK, 4-Leads, Body 9x10.2mm, Pitch 2.54mm, Lead Span 14.9mm, IPC Medium Density)
footprint DDPAK-EB3_L (D2-PAK, 4-Leads, Body 9x10.2mm, Pitch 2.54mm, Lead Span 14.9mm, IPC High Density)
footprint DDPAK-EB3_M (D2-PAK, 4-Leads, Body 9x10.2mm, Pitch 2.54mm, Lead Span 14.9mm, IPC Low Density)
pins: 1 VIN (power), 2 GND (power), 3 VOUT (power), 4 GND (power)

## MCP1826S-2502E/AB
designator U?
1000 mA, Low Voltage, Low Quiescent Current LDO Regulator, 3-Pin TO-220, Extended Temperature
footprint TO-220-AB3 (TO, Thru-Hole, Vertical, Heatsink Mounted; 3 In-Line Leads; Pitch 2.54 mm)
pins: 1 VIN (power), 2 GND (power), 3 VOUT (power)

## MCP1826S-2502E/DB
designator U?
1000 mA, Low Voltage, Low Quiescent Current LDO Regulator, 3-Pin SOT-223, Extended Temperature
footprint SOT-223-DB3_N (SOT223, 4-Leads, Body 6.5x3.5mm, Pitch 2.3mm, Lead Span 7mm, IPC Medium Density)
footprint SOT-223-DB3_L (SOT223, 4-Leads, Body 6.5x3.5mm, Pitch 2.3mm, Lead Span 7mm, IPC High Density)
footprint SOT-223-DB3_M (SOT223, 4-Leads, Body 6.5x3.5mm, Pitch 2.3mm, Lead Span 7mm, IPC Low Density)
pins: 1 VIN (power), 2 GND (power), 3 VOUT (power), 4 GND (power)

## MCP1826S-2502E/EB
designator U?
1000 mA, Low Voltage, Low Quiescent Current LDO Regulator, 3-Pin DDPAK, Extended Temperature
footprint DDPAK-EB3_N (D2-PAK, 4-Leads, Body 9x10.2mm, Pitch 2.54mm, Lead Span 14.9mm, IPC Medium Density)
footprint DDPAK-EB3_L (D2-PAK, 4-Leads, Body 9x10.2mm, Pitch 2.54mm, Lead Span 14.9mm, IPC High Density)
footprint DDPAK-EB3_M (D2-PAK, 4-Leads, Body 9x10.2mm, Pitch 2.54mm, Lead Span 14.9mm, IPC Low Density)
pins: 1 VIN (power), 2 GND (power), 3 VOUT (power), 4 GND (power)

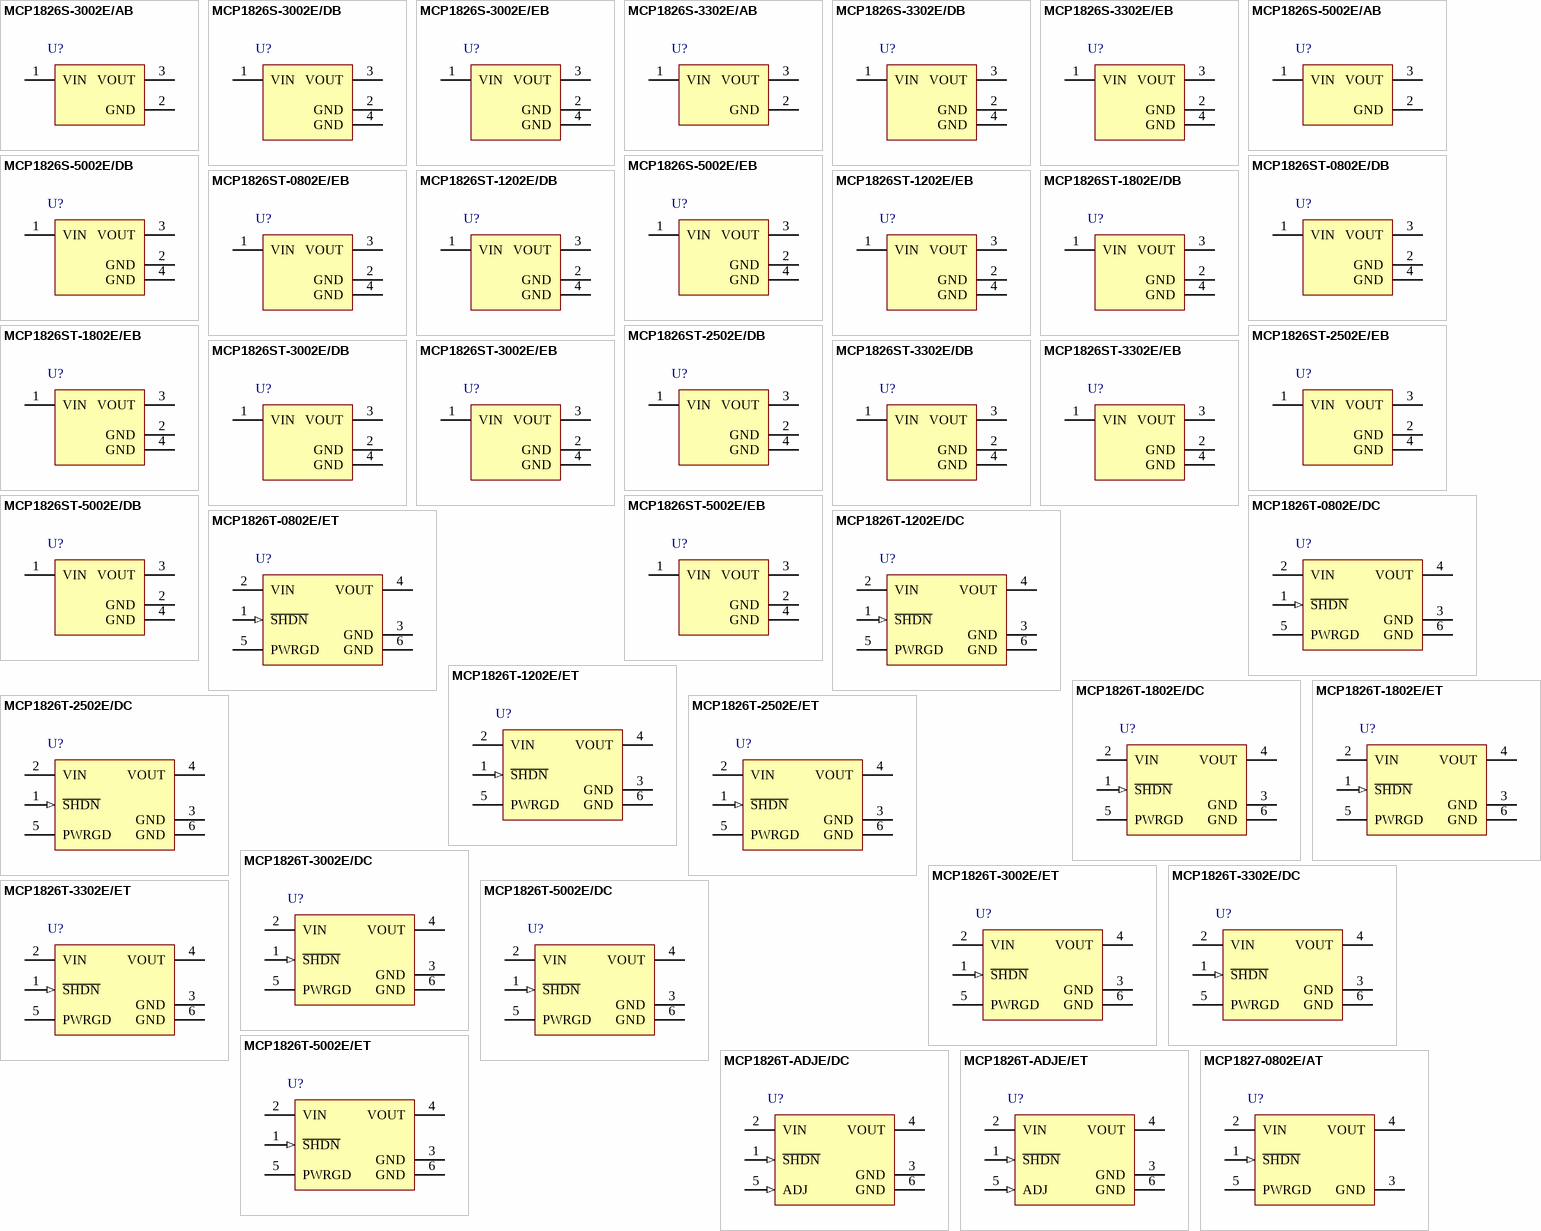
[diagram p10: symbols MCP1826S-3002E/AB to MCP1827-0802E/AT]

## MCP1826S-3002E/AB
designator U?
1000 mA, Low Voltage, Low Quiescent Current LDO Regulator, 3-Pin TO-220, Extended Temperature
footprint TO-220-AB3 (TO, Thru-Hole, Vertical, Heatsink Mounted; 3 In-Line Leads; Pitch 2.54 mm)
pins: 1 VIN (power), 2 GND (power), 3 VOUT (power)

## MCP1826S-3002E/DB
designator U?
1000 mA, Low Voltage, Low Quiescent Current LDO Regulator, 3-Pin SOT-223, Extended Temperature
footprint SOT-223-DB3_N (SOT223, 4-Leads, Body 6.5x3.5mm, Pitch 2.3mm, Lead Span 7mm, IPC Medium Density)
footprint SOT-223-DB3_L (SOT223, 4-Leads, Body 6.5x3.5mm, Pitch 2.3mm, Lead Span 7mm, IPC High Density)
footprint SOT-223-DB3_M (SOT223, 4-Leads, Body 6.5x3.5mm, Pitch 2.3mm, Lead Span 7mm, IPC Low Density)
pins: 1 VIN (power), 2 GND (power), 3 VOUT (power), 4 GND (power)

## MCP1826S-3002E/EB
designator U?
1000 mA, Low Voltage, Low Quiescent Current LDO Regulator, 3-Pin DDPAK, Extended Temperature
footprint DDPAK-EB3_N (D2-PAK, 4-Leads, Body 9x10.2mm, Pitch 2.54mm, Lead Span 14.9mm, IPC Medium Density)
footprint DDPAK-EB3_L (D2-PAK, 4-Leads, Body 9x10.2mm, Pitch 2.54mm, Lead Span 14.9mm, IPC High Density)
footprint DDPAK-EB3_M (D2-PAK, 4-Leads, Body 9x10.2mm, Pitch 2.54mm, Lead Span 14.9mm, IPC Low Density)
pins: 1 VIN (power), 2 GND (power), 3 VOUT (power), 4 GND (power)

## MCP1826S-3302E/AB
designator U?
1000 mA, Low Voltage, Low Quiescent Current LDO Regulator, 3-Pin TO-220, Extended Temperature
footprint TO-220-AB3 (TO, Thru-Hole, Vertical, Heatsink Mounted; 3 In-Line Leads; Pitch 2.54 mm)
pins: 1 VIN (power), 2 GND (power), 3 VOUT (power)

## MCP1826S-3302E/DB
designator U?
1000 mA, Low Voltage, Low Quiescent Current LDO Regulator, 3-Pin SOT-223, Extended Temperature
footprint SOT-223-DB3_N (SOT223, 4-Leads, Body 6.5x3.5mm, Pitch 2.3mm, Lead Span 7mm, IPC Medium Density)
footprint SOT-223-DB3_L (SOT223, 4-Leads, Body 6.5x3.5mm, Pitch 2.3mm, Lead Span 7mm, IPC High Density)
footprint SOT-223-DB3_M (SOT223, 4-Leads, Body 6.5x3.5mm, Pitch 2.3mm, Lead Span 7mm, IPC Low Density)
pins: 1 VIN (power), 2 GND (power), 3 VOUT (power), 4 GND (power)

## MCP1826S-3302E/EB
designator U?
1000 mA, Low Voltage, Low Quiescent Current LDO Regulator, 3-Pin DDPAK, Extended Temperature
footprint DDPAK-EB3_N (D2-PAK, 4-Leads, Body 9x10.2mm, Pitch 2.54mm, Lead Span 14.9mm, IPC Medium Density)
footprint DDPAK-EB3_L (D2-PAK, 4-Leads, Body 9x10.2mm, Pitch 2.54mm, Lead Span 14.9mm, IPC High Density)
footprint DDPAK-EB3_M (D2-PAK, 4-Leads, Body 9x10.2mm, Pitch 2.54mm, Lead Span 14.9mm, IPC Low Density)
pins: 1 VIN (power), 2 GND (power), 3 VOUT (power), 4 GND (power)

## MCP1826S-5002E/AB
designator U?
1000 mA, Low Voltage, Low Quiescent Current LDO Regulator, 3-Pin TO-220, Extended Temperature
footprint TO-220-AB3 (TO, Thru-Hole, Vertical, Heatsink Mounted; 3 In-Line Leads; Pitch 2.54 mm)
pins: 1 VIN (power), 2 GND (power), 3 VOUT (power)

## MCP1826S-5002E/DB
designator U?
1000 mA, Low Voltage, Low Quiescent Current LDO Regulator, 3-Pin SOT-223, Extended Temperature
footprint SOT-223-DB3_N (SOT223, 4-Leads, Body 6.5x3.5mm, Pitch 2.3mm, Lead Span 7mm, IPC Medium Density)
footprint SOT-223-DB3_L (SOT223, 4-Leads, Body 6.5x3.5mm, Pitch 2.3mm, Lead Span 7mm, IPC High Density)
footprint SOT-223-DB3_M (SOT223, 4-Leads, Body 6.5x3.5mm, Pitch 2.3mm, Lead Span 7mm, IPC Low Density)
pins: 1 VIN (power), 2 GND (power), 3 VOUT (power), 4 GND (power)

## MCP1826S-5002E/EB
designator U?
1000 mA, Low Voltage, Low Quiescent Current LDO Regulator, 3-Pin DDPAK, Extended Temperature
footprint DDPAK-EB3_N (D2-PAK, 4-Leads, Body 9x10.2mm, Pitch 2.54mm, Lead Span 14.9mm, IPC Medium Density)
footprint DDPAK-EB3_L (D2-PAK, 4-Leads, Body 9x10.2mm, Pitch 2.54mm, Lead Span 14.9mm, IPC High Density)
footprint DDPAK-EB3_M (D2-PAK, 4-Leads, Body 9x10.2mm, Pitch 2.54mm, Lead Span 14.9mm, IPC Low Density)
pins: 1 VIN (power), 2 GND (power), 3 VOUT (power), 4 GND (power)

## MCP1826ST-0802E/DB
designator U?
1000 mA, Low Voltage, Low Quiescent Current LDO Regulator, 3-Pin SOT-223, Extended Temperature, Tape and Reel
footprint SOT-223-DB3_N (SOT223, 4-Leads, Body 6.5x3.5mm, Pitch 2.3mm, Lead Span 7mm, IPC Medium Density)
footprint SOT-223-DB3_L (SOT223, 4-Leads, Body 6.5x3.5mm, Pitch 2.3mm, Lead Span 7mm, IPC High Density)
footprint SOT-223-DB3_M (SOT223, 4-Leads, Body 6.5x3.5mm, Pitch 2.3mm, Lead Span 7mm, IPC Low Density)
pins: 1 VIN (power), 2 GND (power), 3 VOUT (power), 4 GND (power)

## MCP1826ST-0802E/EB
designator U?
1000 mA, Low Voltage, Low Quiescent Current LDO Regulator, 3-Pin DDPAK, Extended Temperature, Tape and Reel
footprint DDPAK-EB3_N (D2-PAK, 4-Leads, Body 9x10.2mm, Pitch 2.54mm, Lead Span 14.9mm, IPC Medium Density)
footprint DDPAK-EB3_L (D2-PAK, 4-Leads, Body 9x10.2mm, Pitch 2.54mm, Lead Span 14.9mm, IPC High Density)
footprint DDPAK-EB3_M (D2-PAK, 4-Leads, Body 9x10.2mm, Pitch 2.54mm, Lead Span 14.9mm, IPC Low Density)
pins: 1 VIN (power), 2 GND (power), 3 VOUT (power), 4 GND (power)

## MCP1826ST-1202E/DB
designator U?
1000 mA, Low Voltage, Low Quiescent Current LDO Regulator, 3-Pin SOT-223, Extended Temperature, Tape and Reel
footprint SOT-223-DB3_N (SOT223, 4-Leads, Body 6.5x3.5mm, Pitch 2.3mm, Lead Span 7mm, IPC Medium Density)
footprint SOT-223-DB3_L (SOT223, 4-Leads, Body 6.5x3.5mm, Pitch 2.3mm, Lead Span 7mm, IPC High Density)
footprint SOT-223-DB3_M (SOT223, 4-Leads, Body 6.5x3.5mm, Pitch 2.3mm, Lead Span 7mm, IPC Low Density)
pins: 1 VIN (power), 2 GND (power), 3 VOUT (power), 4 GND (power)

## MCP1826ST-1202E/EB
designator U?
1000 mA, Low Voltage, Low Quiescent Current LDO Regulator, 3-Pin DDPAK, Extended Temperature, Tape and Reel
footprint DDPAK-EB3_N (D2-PAK, 4-Leads, Body 9x10.2mm, Pitch 2.54mm, Lead Span 14.9mm, IPC Medium Density)
footprint DDPAK-EB3_L (D2-PAK, 4-Leads, Body 9x10.2mm, Pitch 2.54mm, Lead Span 14.9mm, IPC High Density)
footprint DDPAK-EB3_M (D2-PAK, 4-Leads, Body 9x10.2mm, Pitch 2.54mm, Lead Span 14.9mm, IPC Low Density)
pins: 1 VIN (power), 2 GND (power), 3 VOUT (power), 4 GND (power)

## MCP1826ST-1802E/DB
designator U?
1000 mA, Low Voltage, Low Quiescent Current LDO Regulator, 3-Pin SOT-223, Extended Temperature, Tape and Reel
footprint SOT-223-DB3_N (SOT223, 4-Leads, Body 6.5x3.5mm, Pitch 2.3mm, Lead Span 7mm, IPC Medium Density)
footprint SOT-223-DB3_L (SOT223, 4-Leads, Body 6.5x3.5mm, Pitch 2.3mm, Lead Span 7mm, IPC High Density)
footprint SOT-223-DB3_M (SOT223, 4-Leads, Body 6.5x3.5mm, Pitch 2.3mm, Lead Span 7mm, IPC Low Density)
pins: 1 VIN (power), 2 GND (power), 3 VOUT (power), 4 GND (power)

## MCP1826ST-1802E/EB
designator U?
1000 mA, Low Voltage, Low Quiescent Current LDO Regulator, 3-Pin DDPAK, Extended Temperature, Tape and Reel
footprint DDPAK-EB3_N (D2-PAK, 4-Leads, Body 9x10.2mm, Pitch 2.54mm, Lead Span 14.9mm, IPC Medium Density)
footprint DDPAK-EB3_L (D2-PAK, 4-Leads, Body 9x10.2mm, Pitch 2.54mm, Lead Span 14.9mm, IPC High Density)
footprint DDPAK-EB3_M (D2-PAK, 4-Leads, Body 9x10.2mm, Pitch 2.54mm, Lead Span 14.9mm, IPC Low Density)
pins: 1 VIN (power), 2 GND (power), 3 VOUT (power), 4 GND (power)

## MCP1826ST-2502E/DB
designator U?
1000 mA, Low Voltage, Low Quiescent Current LDO Regulator, 3-Pin SOT-223, Extended Temperature, Tape and Reel
footprint SOT-223-DB3_N (SOT223, 4-Leads, Body 6.5x3.5mm, Pitch 2.3mm, Lead Span 7mm, IPC Medium Density)
footprint SOT-223-DB3_L (SOT223, 4-Leads, Body 6.5x3.5mm, Pitch 2.3mm, Lead Span 7mm, IPC High Density)
footprint SOT-223-DB3_M (SOT223, 4-Leads, Body 6.5x3.5mm, Pitch 2.3mm, Lead Span 7mm, IPC Low Density)
pins: 1 VIN (power), 2 GND (power), 3 VOUT (power), 4 GND (power)

## MCP1826ST-2502E/EB
designator U?
1000 mA, Low Voltage, Low Quiescent Current LDO Regulator, 3-Pin DDPAK, Extended Temperature, Tape and Reel
footprint DDPAK-EB3_N (D2-PAK, 4-Leads, Body 9x10.2mm, Pitch 2.54mm, Lead Span 14.9mm, IPC Medium Density)
footprint DDPAK-EB3_L (D2-PAK, 4-Leads, Body 9x10.2mm, Pitch 2.54mm, Lead Span 14.9mm, IPC High Density)
footprint DDPAK-EB3_M (D2-PAK, 4-Leads, Body 9x10.2mm, Pitch 2.54mm, Lead Span 14.9mm, IPC Low Density)
pins: 1 VIN (power), 2 GND (power), 3 VOUT (power), 4 GND (power)

## MCP1826ST-3002E/DB
designator U?
1000 mA, Low Voltage, Low Quiescent Current LDO Regulator, 3-Pin SOT-223, Extended Temperature, Tape and Reel
footprint SOT-223-DB3_N (SOT223, 4-Leads, Body 6.5x3.5mm, Pitch 2.3mm, Lead Span 7mm, IPC Medium Density)
footprint SOT-223-DB3_L (SOT223, 4-Leads, Body 6.5x3.5mm, Pitch 2.3mm, Lead Span 7mm, IPC High Density)
footprint SOT-223-DB3_M (SOT223, 4-Leads, Body 6.5x3.5mm, Pitch 2.3mm, Lead Span 7mm, IPC Low Density)
pins: 1 VIN (power), 2 GND (power), 3 VOUT (power), 4 GND (power)

## MCP1826ST-3002E/EB
designator U?
1000 mA, Low Voltage, Low Quiescent Current LDO Regulator, 3-Pin DDPAK, Extended Temperature, Tape and Reel
footprint DDPAK-EB3_N (D2-PAK, 4-Leads, Body 9x10.2mm, Pitch 2.54mm, Lead Span 14.9mm, IPC Medium Density)
footprint DDPAK-EB3_L (D2-PAK, 4-Leads, Body 9x10.2mm, Pitch 2.54mm, Lead Span 14.9mm, IPC High Density)
footprint DDPAK-EB3_M (D2-PAK, 4-Leads, Body 9x10.2mm, Pitch 2.54mm, Lead Span 14.9mm, IPC Low Density)
pins: 1 VIN (power), 2 GND (power), 3 VOUT (power), 4 GND (power)

## MCP1826ST-3302E/DB
designator U?
1000 mA, Low Voltage, Low Quiescent Current LDO Regulator, 3-Pin SOT-223, Extended Temperature, Tape and Reel
footprint SOT-223-DB3_N (SOT223, 4-Leads, Body 6.5x3.5mm, Pitch 2.3mm, Lead Span 7mm, IPC Medium Density)
footprint SOT-223-DB3_L (SOT223, 4-Leads, Body 6.5x3.5mm, Pitch 2.3mm, Lead Span 7mm, IPC High Density)
footprint SOT-223-DB3_M (SOT223, 4-Leads, Body 6.5x3.5mm, Pitch 2.3mm, Lead Span 7mm, IPC Low Density)
pins: 1 VIN (power), 2 GND (power), 3 VOUT (power), 4 GND (power)

## MCP1826ST-3302E/EB
designator U?
1000 mA, Low Voltage, Low Quiescent Current LDO Regulator, 3-Pin DDPAK, Extended Temperature, Tape and Reel
footprint DDPAK-EB3_N (D2-PAK, 4-Leads, Body 9x10.2mm, Pitch 2.54mm, Lead Span 14.9mm, IPC Medium Density)
footprint DDPAK-EB3_L (D2-PAK, 4-Leads, Body 9x10.2mm, Pitch 2.54mm, Lead Span 14.9mm, IPC High Density)
footprint DDPAK-EB3_M (D2-PAK, 4-Leads, Body 9x10.2mm, Pitch 2.54mm, Lead Span 14.9mm, IPC Low Density)
pins: 1 VIN (power), 2 GND (power), 3 VOUT (power), 4 GND (power)

## MCP1826ST-5002E/DB
designator U?
1000 mA, Low Voltage, Low Quiescent Current LDO Regulator, 3-Pin SOT-223, Extended Temperature, Tape and Reel
footprint SOT-223-DB3_N (SOT223, 4-Leads, Body 6.5x3.5mm, Pitch 2.3mm, Lead Span 7mm, IPC Medium Density)
footprint SOT-223-DB3_L (SOT223, 4-Leads, Body 6.5x3.5mm, Pitch 2.3mm, Lead Span 7mm, IPC High Density)
footprint SOT-223-DB3_M (SOT223, 4-Leads, Body 6.5x3.5mm, Pitch 2.3mm, Lead Span 7mm, IPC Low Density)
pins: 1 VIN (power), 2 GND (power), 3 VOUT (power), 4 GND (power)

## MCP1826ST-5002E/EB
designator U?
1000 mA, Low Voltage, Low Quiescent Current LDO Regulator, 3-Pin DDPAK, Extended Temperature, Tape and Reel
footprint DDPAK-EB3_N (D2-PAK, 4-Leads, Body 9x10.2mm, Pitch 2.54mm, Lead Span 14.9mm, IPC Medium Density)
footprint DDPAK-EB3_L (D2-PAK, 4-Leads, Body 9x10.2mm, Pitch 2.54mm, Lead Span 14.9mm, IPC High Density)
footprint DDPAK-EB3_M (D2-PAK, 4-Leads, Body 9x10.2mm, Pitch 2.54mm, Lead Span 14.9mm, IPC Low Density)
pins: 1 VIN (power), 2 GND (power), 3 VOUT (power), 4 GND (power)

## MCP1826T-0802E/DC
designator U?
1000 mA, Low Voltage, Low Quiescent Current LDO Regulator, 5-Pin SOT-223, Extended Temperature, Tape and Reel
footprint SOT-223-DC5_N (SOT223, 6-Leads, Body 6.5x3.5mm, Pitch 1.27mm, Lead Span 7mm, IPC Medium Density)
footprint SOT-223-DC5_L (SOT223, 6-Leads, Body 6.5x3.5mm, Pitch 1.27mm, Lead Span 7mm, IPC High Density)
footprint SOT-223-DC5_M (SOT223, 6-Leads, Body 6.5x3.5mm, Pitch 1.27mm, Lead Span 7mm, IPC Low Density)
pins: 1 ~{SHDN} (in), 2 VIN (power), 3 GND (power), 4 VOUT (power), 5 PWRGD (power), 6 GND (power)

## MCP1826T-0802E/ET
designator U?
1000 mA, Low Voltage, Low Quiescent Current LDO Regulator, 5-Pin DDPAK, Extended Temperature, Tape and Reel
footprint DDPAK-ET5_N (D2-PAK, 6-Leads, Body 9x10.2mm, Pitch 1.7mm, Lead Span 14.9mm, IPC Medium Density)
footprint DDPAK-ET5_L (D2-PAK, 6-Leads, Body 9x10.2mm, Pitch 1.7mm, Lead Span 14.9mm, IPC High Density)
footprint DDPAK-ET5_M (D2-PAK, 6-Leads, Body 9x10.2mm, Pitch 1.7mm, Lead Span 14.9mm, IPC Low Density)
pins: 1 ~{SHDN} (in), 2 VIN (power), 3 GND (power), 4 VOUT (power), 5 PWRGD (power), 6 GND (power)

## MCP1826T-1202E/DC
designator U?
1000 mA, Low Voltage, Low Quiescent Current LDO Regulator, 5-Pin SOT-223, Extended Temperature, Tape and Reel
footprint SOT-223-DC5_N (SOT223, 6-Leads, Body 6.5x3.5mm, Pitch 1.27mm, Lead Span 7mm, IPC Medium Density)
footprint SOT-223-DC5_L (SOT223, 6-Leads, Body 6.5x3.5mm, Pitch 1.27mm, Lead Span 7mm, IPC High Density)
footprint SOT-223-DC5_M (SOT223, 6-Leads, Body 6.5x3.5mm, Pitch 1.27mm, Lead Span 7mm, IPC Low Density)
pins: 1 ~{SHDN} (in), 2 VIN (power), 3 GND (power), 4 VOUT (power), 5 PWRGD (power), 6 GND (power)

## MCP1826T-1202E/ET
designator U?
1000 mA, Low Voltage, Low Quiescent Current LDO Regulator, 5-Pin DDPAK, Extended Temperature, Tape and Reel
footprint DDPAK-ET5_N (D2-PAK, 6-Leads, Body 9x10.2mm, Pitch 1.7mm, Lead Span 14.9mm, IPC Medium Density)
footprint DDPAK-ET5_L (D2-PAK, 6-Leads, Body 9x10.2mm, Pitch 1.7mm, Lead Span 14.9mm, IPC High Density)
footprint DDPAK-ET5_M (D2-PAK, 6-Leads, Body 9x10.2mm, Pitch 1.7mm, Lead Span 14.9mm, IPC Low Density)
pins: 1 ~{SHDN} (in), 2 VIN (power), 3 GND (power), 4 VOUT (power), 5 PWRGD (power), 6 GND (power)

## MCP1826T-1802E/DC
designator U?
1000 mA, Low Voltage, Low Quiescent Current LDO Regulator, 5-Pin SOT-223, Extended Temperature, Tape and Reel
footprint SOT-223-DC5_N (SOT223, 6-Leads, Body 6.5x3.5mm, Pitch 1.27mm, Lead Span 7mm, IPC Medium Density)
footprint SOT-223-DC5_L (SOT223, 6-Leads, Body 6.5x3.5mm, Pitch 1.27mm, Lead Span 7mm, IPC High Density)
footprint SOT-223-DC5_M (SOT223, 6-Leads, Body 6.5x3.5mm, Pitch 1.27mm, Lead Span 7mm, IPC Low Density)
pins: 1 ~{SHDN} (in), 2 VIN (power), 3 GND (power), 4 VOUT (power), 5 PWRGD (power), 6 GND (power)

## MCP1826T-1802E/ET
designator U?
1000 mA, Low Voltage, Low Quiescent Current LDO Regulator, 5-Pin DDPAK, Extended Temperature, Tape and Reel
footprint DDPAK-ET5_N (D2-PAK, 6-Leads, Body 9x10.2mm, Pitch 1.7mm, Lead Span 14.9mm, IPC Medium Density)
footprint DDPAK-ET5_L (D2-PAK, 6-Leads, Body 9x10.2mm, Pitch 1.7mm, Lead Span 14.9mm, IPC High Density)
footprint DDPAK-ET5_M (D2-PAK, 6-Leads, Body 9x10.2mm, Pitch 1.7mm, Lead Span 14.9mm, IPC Low Density)
pins: 1 ~{SHDN} (in), 2 VIN (power), 3 GND (power), 4 VOUT (power), 5 PWRGD (power), 6 GND (power)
